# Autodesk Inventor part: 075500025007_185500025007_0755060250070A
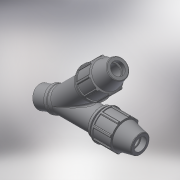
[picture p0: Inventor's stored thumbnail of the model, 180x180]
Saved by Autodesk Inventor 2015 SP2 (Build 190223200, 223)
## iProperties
Created: 2017-02
Part Number: 075500025007_185500025007_0755060250070A
Material: Generic
Description: PLASSON Y FITTING 25-25-3/4"
Document SubType Name: Modeling
Designer: KIM
Mass: 111.65 g
Surface Area: 364.865 cm^2
Volume: 111.65 cm^3
Density: 1 g/cm^3
Appearance: Default
Author: KIM
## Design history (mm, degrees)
derived "07550.ipt"
feature "Solid1::07550.ipt"
tag "TaggingFeature1"
body "Solid1"
other parameters: "d2" = 25, "d4" = 10.41667, "d5" = 25, "d7" = 54, "d11" = 4.16667, "d13" = 120 deg, "d14" = 37.5, "d15" = 12 deg, "d16" = 46.98, "d18" = 1.25, "d19" = 35 deg, "d20" = 17.5 deg, "d21" = 50.22, "d23" = 0, "d25" = 360 deg, "d27" = 1.08, "d33" = 0.5, "d42" = 31.25, "d43" = 1.62, "d46" = 0.75, "d51" = 125, "d68" = 4.16667, "d91" = 40.5, "d93" = 58, "d95" = 18.5087, "d98" = 2.7, "d99" = 0, "d101" = 45 deg, "d103" = 2.7, "d104" = 160 deg, "d105" = 26.441, "d106" = 30.40715, "d107" = 18, "d108" = 30.375, "d109" = 18.5087, "d110" = 40.5, "d111" = 9.1125, "d113" = 0.52882, "d116" = 1.08, "d_" = 25, "E_" = 54, "A_" = 125, "l_" = 58, "l_2" = 18, "R_" = 26.441
